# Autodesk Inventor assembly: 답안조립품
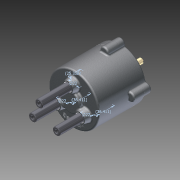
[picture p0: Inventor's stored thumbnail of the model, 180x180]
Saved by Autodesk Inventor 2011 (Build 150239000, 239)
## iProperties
Created: 2015-05
Part Number: 답안조립품
Document SubType Name: Assembly
Designer: Administrator
Author: Administrator
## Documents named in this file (14)
- C:\Documents and Settings\Administrator\바탕 화면\류성호Inventor1급\답안조립품.iam
- C:\Documents and Settings\Administrator\바탕 화면\류성호Inventor1급\2014-02-20 1급 공용부품\몸체.ipt
- C:\Documents and Settings\Administrator\바탕 화면\류성호Inventor1급\2014-02-20 1급 공용부품\커버.ipt
- C:\Documents and Settings\Administrator\바탕 화면\류성호Inventor1급\2014-02-20 1급 공용부품\오일실.ipt
- C:\Documents and Settings\Administrator\바탕 화면\류성호Inventor1급\2014-02-20 1급 공용부품\베어링 NA 4900.ipt
- C:\Documents and Settings\Administrator\바탕 화면\류성호Inventor1급\2014-02-20 1급 공용부품\메인 축.ipt
- C:\Documents and Settings\Administrator\바탕 화면\류성호Inventor1급\2014-02-20 1급 공용부품\판캠.ipt
- C:\Documents and Settings\Administrator\바탕 화면\류성호Inventor1급\2014-02-20 1급 공용부품\멈춤링 22 x 1.2.ipt
- C:\Documents and Settings\Administrator\바탕 화면\류성호Inventor1급\2014-02-20 1급 공용부품\멈춤링 10 x 1.ipt
- C:\Documents and Settings\Administrator\바탕 화면\류성호Inventor1급\2014-02-20 1급 공용부품\슬라이드 축.ipt
- C:\Documents and Settings\Administrator\바탕 화면\류성호Inventor1급\가변 스프링-01.ipt
- C:\Documents and Settings\Administrator\바탕 화면\류성호Inventor1급\가변 스프링-02.ipt
- C:\Documents and Settings\Administrator\바탕 화면\류성호Inventor1급\가변 스프링-03.ipt
- C:\Documents and Settings\Administrator\바탕 화면\류성호Inventor1급\2014-02-20 1급 공용부품\M5x0.5x20.ipt
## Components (7 placed, 4 different names)
1. 가변 스프링-01:1
2. 가변 스프링-02:1
3. 가변 스프링-03:1
4. M5x0.5x20:1
5. M5x0.5x20:2
6. M5x0.5x20:3
7. M5x0.5x20:4
